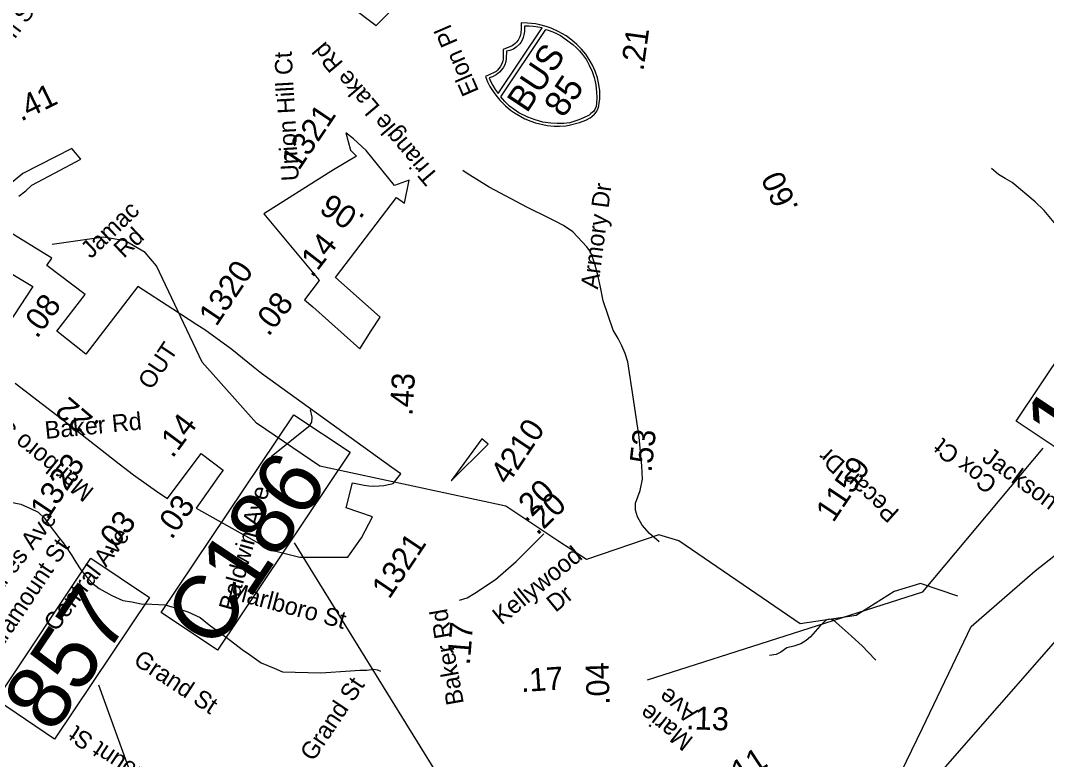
# Model space of a CAD drawing. Extents: x 1716282 to 1717158, y 799307 to 801078.
# Drawn here: x 1716895.7 to 1716976.7, y 800865.9 to 800924.3 of the extents above; entities that cross this region are included whole.
import ezdxf

# ---------------------------------------------------------------- set-up
doc = ezdxf.new("R2010")
doc.units = 0
for name, color, linetype in [('Exist Boundary Political City Limit New Hole', 7, 'Continuous'), ('Exist Hydrographic Misc Water Feature', 7, 'Continuous'), ('Exist Road Non-System Type 51', 7, 'Continuous'), ('Exist Road Non-System Type 51 Label', 7, 'Continuous'), ('Exist Road Primary Interstate Mileage Hundredths English Label', 7, 'Continuous'), ('Exist Road Primary Interstate Service Mileage Label', 7, 'Continuous'), ('Exist Road Primary Interstate Shield CELL', 7, 'Continuous'), ('Exist Road Primary Interstate Shield Number Label', 7, 'Continuous'), ('Exist Road Primary Interstate Structure Culvert Number Label', 7, 'Continuous'), ('Exist Road Primary US Structure Standard Bridge Number Label', 7, 'Continuous'), ('Exist Road Secondary Mileage Hundredths English Label', 7, 'Continuous'), ('Exist Road Secondary Mileage Tenths English Label', 7, 'Continuous'), ('Exist Road Secondary Structure Private Number Label', 7, 'Continuous'), ('Exist Road Secondary Structure Standard Bridge Number Label', 7, 'Continuous'), ('Exist Road Secondary Type 51 Label', 7, 'Continuous'), ('Exist Road Secondary Type 51 Number Label', 7, 'Continuous'), ('Exist Utilities Electrical Transmission Line', 7, 'Continuous')]:
    doc.layers.add(name, color=color, linetype=linetype)

msp = doc.modelspace()

# ---------------------------------------------------------------- linework, layer by layer
at = {"layer": 'Exist Boundary Political City Limit New Hole'}
for points in [[(1716926.548, 800926.628), (1716927.986, 800925.74), (1716928.639, 800925.355), (1716928.771, 800925.396), (1716931.477, 800928.47), (1716928.999, 800930.443), (1716931.031, 800932.976), (1716928.93, 800935.191), (1716928.099, 800935.987), (1716924.843, 800932.956), (1716921.977, 800930.288), (1716922.19, 800930.123), (1716921.362, 800929.315), (1716919.347, 800927.339), (1716920.081, 800926.73), (1716923.814, 800923.902), (1716926.548, 800926.628)], [(1716922.028, 800914.945), (1716921.442, 800915.418), (1716921.809, 800914.049), (1716922.268, 800913.565), (1716920.448, 800912.486), (1716920.03, 800912.221), (1716914.965, 800909.014), (1716919.302, 800903.797), (1716919.337, 800903.756), (1716918.172, 800902.224), (1716918.821, 800901.659), (1716922.525, 800898.348), (1716923.441, 800899.768), (1716924.135, 800900.852), (1716920.624, 800903.998), (1716925.425, 800910.305), (1716926.048, 800909.858), (1716926.43, 800911.669), (1716925.267, 800911.244), (1716923.026, 800914.015), (1716922.028, 800914.945)], [(1716895.623, 800910.42), (1716896.181, 800910.845), (1716896.65, 800911.27), (1716898.422, 800912.232), (1716900.498, 800913.331), (1716899.803, 800914.181), (1716895.92, 800912.206), (1716894.561, 800911.063)], [(1716895.333, 800895.637), (1716899.629, 800892.323), (1716903.548, 800889.268), (1716904.657, 800888.401), (1716906.674, 800886.986), (1716907.363, 800886.527), (1716910.01, 800890.071), (1716911.738, 800888.753), (1716911.488, 800888.41), (1716910.874, 800887.554), (1716910.439, 800886.933), (1716909.627, 800885.766), (1716915.483, 800882.475), (1716917.794, 800881.89), (1716920.139, 800881.9), (1716921.589, 800881.898), (1716921.784, 800882.16), (1716922.654, 800883.422), (1716923.529, 800885.081), (1716921.453, 800885.799), (1716921.943, 800887.752), (1716922.879, 800887.57), (1716923.243, 800887.525), (1716923.61, 800887.507), (1716924.068, 800887.518), (1716924.433, 800887.558), (1716924.794, 800887.622), (1716925.062, 800887.684), (1716925.165, 800887.709), (1716925.778, 800888.479), (1716925.069, 800888.986), (1716922.33, 800890.943), (1716914.77, 800896.405), (1716914.124, 800896.931), (1716912.431, 800898.286), (1716910.301, 800899.841), (1716909.676, 800900.246), (1716907.77, 800901.482), (1716905.02, 800903.264), (1716900.899, 800897.933), (1716898.619, 800899.751), (1716900.847, 800902.653), (1716897.828, 800904.931), (1716898.214, 800905.515), (1716893.19, 800908.583)], [(1716890.966, 800906.728), (1716896.721, 800903.262), (1716893.13, 800897.851)], [(1716929.755, 800887.909), (1716932.665, 800890.822), (1716932.168, 800891.227), (1716929.755, 800887.909)]]:
    msp.add_lwpolyline(points, dxfattribs=at)
at = {"layer": 'Exist Hydrographic Misc Water Feature'}
for points in [[(1716946.168, 800883.092), (1716945.395, 800883.76), (1716944.831, 800884.427), (1716944.46, 800885.065), (1716944.298, 800885.599), (1716944.295, 800886.161), (1716944.653, 800887.149), (1716944.856, 800888.063), (1716944.803, 800889.118), (1716944.703, 800890.205), (1716944.588, 800891.373), (1716944.146, 800894.379), (1716943.697, 800897.322), (1716943.488, 800897.991), (1716943.229, 800898.588), (1716942.929, 800899.179), (1716942.534, 800899.835), (1716941.749, 800902.13), (1716941.543, 800903.219), (1716941.321, 800904.179), (1716941.113, 800904.953), (1716940.925, 800905.502), (1716940.746, 800906.012), (1716940.461, 800906.416), (1716939.339, 800907.603), (1716938.621, 800908.094), (1716937.95, 800908.449), (1716937.47, 800908.672), (1716935.764, 800909.518), (1716932.75, 800911.123), (1716931, 800912.212), (1716930.665, 800912.441)], [(1716978.277, 800907.212), (1716976.554, 800909.267), (1716975.838, 800909.968), (1716974.028, 800911.484), (1716973.469, 800911.797), (1716972.95, 800912.116), (1716972.401, 800912.598)], [(1716938.162, 800883.187), (1716934.072, 800885.916), (1716919.378, 800889.067), (1716914.389, 800892.477), (1716910.099, 800897.303), (1716906.476, 800904.911), (1716905.584, 800905.96), (1716904.015, 800906.871), (1716902.31, 800907.175), (1716898.24, 800906.584)], [(1716895.118, 800886.2), (1716895.768, 800886.066), (1716896.534, 800885.744), (1716897.148, 800885.458), (1716897.629, 800884.981), (1716898.099, 800884.335), (1716898.782, 800883.436), (1716899.128, 800883.019), (1716899.471, 800882.497), (1716899.807, 800882.015), (1716900.112, 800881.485), (1716900.51, 800880.89), (1716900.965, 800880.326), (1716901.382, 800879.859), (1716901.961, 800879.42), (1716902.956, 800878.868), (1716903.817, 800878.479), (1716904.547, 800878.359), (1716905.261, 800878.216), (1716906.121, 800878.181), (1716907.175, 800878.119), (1716908.143, 800877.833), (1716908.958, 800877.582), (1716909.938, 800877.111), (1716910.643, 800876.549), (1716911.603, 800875.846), (1716912.325, 800875.309), (1716913.245, 800874.597), (1716913.815, 800874.197), (1716914.745, 800873.552), (1716915.759, 800873.128), (1716916.436, 800872.831), (1716919.452, 800872.743), (1716921.798, 800872.912), (1716922.539, 800872.961), (1716923.078, 800872.972), (1716923.651, 800873.034), (1716923.931, 800872.979), (1716924.179, 800872.878)], [(1716969.744, 800878.807), (1716966.787, 800879.81), (1716964.716, 800879.173), (1716961.707, 800877.278), (1716957.305, 800876.629), (1716947.713, 800883.172), (1716946.142, 800883.666), (1716940.425, 800881.716), (1716938.162, 800883.187)]]:
    msp.add_lwpolyline(points, dxfattribs=at)
at = {"layer": 'Exist Road Non-System Type 51'}
for points in [[(1716918.62, 800893.534), (1716918.75, 800892.947), (1716918.713, 800892.559), (1716918.49, 800892.185), (1716915.546, 800889.82)], [(1716930.401, 800878.486), (1716931.019, 800878.685), (1716931.625, 800879.036), (1716933.241, 800880.129), (1716934.869, 800881.55), (1716937.054, 800883.732)], [(1716963.275, 800873.743), (1716962.636, 800874.402), (1716962.205, 800874.861), (1716961.315, 800875.677), (1716960.385, 800876.52), (1716959.934, 800876.913), (1716959.631, 800876.987), (1716959.365, 800876.945), (1716959.113, 800876.706), (1716958.847, 800876.445), (1716958.11, 800875.591), (1716957.78, 800875.295), (1716957.336, 800875.042), (1716956.806, 800874.858), (1716956.24, 800874.727), (1716955.773, 800874.376), (1716955.413, 800874.21), (1716954.882, 800874.127)]]:
    msp.add_lwpolyline(points, dxfattribs=at)
at = {"layer": 'Exist Road Primary Interstate Shield CELL'}
for points in [[(1716941.213, 800917.065), (1716941.279, 800917.187), (1716941.351, 800917.36), (1716941.402, 800917.542), (1716941.441, 800917.763), (1716941.47, 800918.107), (1716941.487, 800918.388), (1716941.486, 800918.726), (1716941.411, 800919.232), (1716941.291, 800919.767), (1716941.102, 800920.294), (1716940.9, 800920.748), (1716940.63, 800921.209), (1716940.366, 800921.62), (1716940.026, 800922.034), (1716939.67, 800922.395), (1716939.269, 800922.726), (1716938.811, 800923.074), (1716938.253, 800923.401), (1716937.642, 800923.675), (1716937.241, 800923.816), (1716936.743, 800923.957), (1716936.41, 800924.023), (1716935.778, 800924.082), (1716935.271, 800924.095), (1716935.282, 800923.612), (1716935.252, 800923.322), (1716935.224, 800923.152), (1716935.16, 800923), (1716935.025, 800922.733), (1716934.914, 800922.582), (1716934.785, 800922.46), (1716934.677, 800922.356), (1716934.561, 800922.289), (1716933.86, 800921.987), (1716933.847, 800921.223), (1716933.824, 800921.076), (1716933.771, 800920.946), (1716933.728, 800920.815), (1716933.615, 800920.627), (1716933.517, 800920.49), (1716933.396, 800920.364), (1716933.297, 800920.267), (1716933.15, 800920.182), (1716932.442, 800919.869), (1716932.609, 800919.448), (1716932.798, 800919.068), (1716933.107, 800918.594), (1716933.366, 800918.254), (1716933.587, 800917.988), (1716934.025, 800917.549), (1716934.43, 800917.202), (1716934.736, 800916.984), (1716935.551, 800916.521), (1716936.022, 800916.329), (1716936.415, 800916.192), (1716937.331, 800915.995), (1716937.881, 800915.94), (1716938.297, 800915.931), (1716938.798, 800915.972), (1716939.048, 800916.008), (1716939.882, 800916.232), (1716940.369, 800916.428), (1716940.718, 800916.612), (1716940.86, 800916.713), (1716941.061, 800916.885)], [(1716932.735, 800919.766), (1716932.85, 800919.497), (1716933.023, 800919.16), (1716933.227, 800918.847), (1716933.459, 800918.511), (1716936.941, 800923.71), (1716936.59, 800923.77), (1716936.232, 800923.822), (1716935.893, 800923.852), (1716935.543, 800923.848), (1716935.531, 800923.433), (1716935.489, 800923.154), (1716935.434, 800922.943), (1716935.37, 800922.777), (1716935.238, 800922.541), (1716935.165, 800922.445), (1716934.885, 800922.18), (1716934.657, 800922.026), (1716934.388, 800921.915), (1716934.125, 800921.854), (1716934.099, 800921.275), (1716934.057, 800921.039), (1716933.97, 800920.793), (1716933.845, 800920.543), (1716933.569, 800920.214), (1716933.287, 800920.001), (1716933.002, 800919.844)], [(1716937.218, 800923.569), (1716937.402, 800923.527), (1716937.78, 800923.385), (1716938.058, 800923.257), (1716938.374, 800923.105), (1716938.86, 800922.759), (1716939.357, 800922.392), (1716939.63, 800922.141), (1716939.864, 800921.893), (1716940.113, 800921.601), (1716940.428, 800921.19), (1716940.645, 800920.767), (1716940.868, 800920.271), (1716941.03, 800919.787), (1716941.094, 800919.581), (1716941.177, 800919.217), (1716941.228, 800918.621), (1716941.251, 800918.195), (1716941.224, 800917.722), (1716941.185, 800917.498), (1716941.093, 800917.269), (1716940.971, 800917.112), (1716940.783, 800916.947), (1716940.63, 800916.814), (1716940.201, 800916.588), (1716939.817, 800916.429), (1716939.103, 800916.213), (1716938.628, 800916.157), (1716938.112, 800916.152), (1716937.605, 800916.18), (1716936.973, 800916.27), (1716936.384, 800916.43), (1716935.786, 800916.659), (1716935.098, 800917.004), (1716934.706, 800917.254), (1716934.35, 800917.526), (1716934.179, 800917.692), (1716933.969, 800917.901), (1716933.659, 800918.246)]]:
    msp.add_lwpolyline(points, close=True, dxfattribs=at)
at = {"layer": 'Exist Road Primary Interstate Structure Culvert Number Label'}
msp.add_line((1716938.452, 800848.887), (1716917.387, 800883.023), dxfattribs=at)
msp.add_lwpolyline([(1716906.855, 800877.507), (1716917.322, 800893.146), (1716921.764, 800890.173), (1716911.297, 800874.534)], close=True, dxfattribs=at)
at = {"layer": 'Exist Road Primary US Structure Standard Bridge Number Label'}
msp.add_line((1716930.657, 800792.469), (1716901.927, 800871.786), dxfattribs=at)
msp.add_lwpolyline([(1716893.815, 800870.614), (1716901.307, 800881.808), (1716905.936, 800878.71), (1716898.444, 800867.516)], close=True, dxfattribs=at)
at = {"layer": 'Exist Road Secondary Structure Private Number Label'}
msp.add_lwpolyline([(1716974.349, 800892.644), (1716981.982, 800904.048), (1716986.639, 800900.931), (1716979.006, 800889.526)], close=True, dxfattribs=at)
msp.add_lwpolyline([(1716945.236, 800872.188), (1716966.974, 800879.147), (1716976.472, 800890.503)], dxfattribs=at)
at = {"layer": 'Exist Road Secondary Structure Standard Bridge Number Label'}
msp.add_line((1716964.807, 800860.796), (1716992.417, 800892.393), dxfattribs=at)
at = {"layer": 'Exist Utilities Electrical Transmission Line'}
msp.add_lwpolyline([(1716944.8, 800799.971), (1716945.692, 800811.122), (1716946.399, 800819.65), (1716947.188, 800829.422), (1716951.09, 800836.913), (1716954.684, 800844.014), (1716957.855, 800849.995), (1716960.182, 800854.593), (1716961.868, 800857.902), (1716966.945, 800868.385), (1716970.788, 800876.406), (1716975.857, 800880.798), (1716979.659, 800883.813)], dxfattribs=at)

# ---------------------------------------------------------------- texts
at = {"layer": 'Exist Boundary Political City Limit New Hole'}
msp.add_text('OUT', height=1.3775, rotation=56.20506, dxfattribs=at).set_placement((1716906.071, 800895.033))
at = {"layer": 'Exist Road Non-System Type 51 Label'}
for s, rotation, p in [('Pam St', 53.3829, (1716893.625, 800920.535)), ('Triangle Lake Rd', 130.26838, (1716928.823, 800912.013)), ('Union Hill Ct', 93.23093, (1716917.726, 800911.64)), ('Armory Dr', 82.57819, (1716941.331, 800903.02)), ('Marlboro St', 141.03594, (1716901.639, 800887.228)), ('Charles Ave', 52.18944, (1716892.522, 800876.971)), ('Central Ave', 52.35306, (1716898.551, 800875.939)), ('Paramount St', 56.20506, (1716893.41, 800873.393)), ('Marlboro St', 345.06802, (1716912.032, 800878.667)), ('Grand St', 326.55755, (1716904.573, 800873.503)), ('Grand St', 56.20506, (1716918.865, 800865.688)), ('Paramount St', 146.53214, (1716909.549, 800862.44))]:
    msp.add_text(s, height=1.3775, rotation=rotation, dxfattribs=at).set_placement(p)
at = {"layer": 'Exist Road Primary Interstate Mileage Hundredths English Label'}
for s, rotation, p in [('.21', 82.1108, (1716944.92, 800920.253)), ('.53', 83.7115, (1716945.555, 800888.545)), ('.04', 91.66842, (1716942.26, 800870.234))]:
    msp.add_text(s, height=1.8125, rotation=rotation, dxfattribs=at).set_placement(p)
at = {"layer": 'Exist Road Primary Interstate Service Mileage Label'}
msp.add_text('.11', height=1.8125, rotation=33.3761, dxfattribs=at).set_placement((1716952.057, 800863.597))
at = {"layer": 'Exist Road Primary Interstate Shield Number Label'}
for s, p in [('BUS', (1716935.72, 800916.913)), ('85', (1716938.626, 800916.528))]:
    msp.add_text(s, height=2.03, rotation=56.20506, dxfattribs=at).set_placement(p)
at = {"layer": 'Exist Road Primary Interstate Structure Culvert Number Label'}
msp.add_text('C186', height=5.075, rotation=56.20506, dxfattribs=at).set_placement((1716911.094, 800874.39))
at = {"layer": 'Exist Road Primary US Structure Standard Bridge Number Label'}
msp.add_text('857', height=5.075, rotation=56.20506, dxfattribs=at).set_placement((1716898.306, 800867.826))
at = {"layer": 'Exist Road Secondary Mileage Hundredths English Label'}
for s, rotation, p in [('.41', 25.92016, (1716895.783, 800916.291)), ('.06', 146.17015, (1716923.039, 800908.821)), ('.14', 53.34477, (1716907.751, 800889.649)), ('.03', 55.47933, (1716907.683, 800883.21)), ('.17', 85.33445, (1716931.212, 800873.326)), ('.17', 3.73987, (1716935.286, 800871.23)), ('.13', 358.12593, (1716948.277, 800868.303))]:
    msp.add_text(s, height=1.8125, rotation=rotation, dxfattribs=at).set_placement(p)
at = {"layer": 'Exist Road Secondary Mileage Tenths English Label'}
for s, rotation, p in [('.60', 114.63469, (1716957.204, 800909.498)), ('.14', 52.17416, (1716918.771, 800903.912)), ('.08', 53.75287, (1716897.045, 800899.095)), ('.08', 52.35953, (1716915.326, 800899.262)), ('.43', 86.45566, (1716926.69, 800893.032)), ('.22', 139.6181, (1716902.09, 800892.468)), ('.20', 44.24855, (1716935.637, 800884.558)), ('.20', 44.24855, (1716936.546, 800883.554)), ('.03', 51.57382, (1716902.869, 800881.992))]:
    msp.add_text(s, height=1.8125, rotation=rotation, dxfattribs=at).set_placement(p)
at = {"layer": 'Exist Road Secondary Structure Private Number Label'}
msp.add_text('196', height=5.075, rotation=56.20506, dxfattribs=at).set_placement((1716978.869, 800889.837))
at = {"layer": 'Exist Road Secondary Type 51 Label'}
for s, rotation, p in [('Elon Pl', 113.44952, (1716931.962, 800918.706)), ('Jamac', 43.51904, (1716901.301, 800905.416)), (' Rd', 43.51904, (1716903.535, 800905.098)), ('Baker Rd', 5.63289, (1716897.728, 800891.23)), ('Cox Ct', 141.71839, (1716972.949, 800887.875)), ('Pecan Dr', 138.01422, (1716965.21, 800885.521)), ('Jackson Lake Rd', 323.82883, (1716971.557, 800889.558)), ('Baldwin Ave', 74.40071, (1716912.697, 800877.529)), ('Kellywood', 39.32041, (1716933.713, 800876.49)), (' Dr', 39.32041, (1716937.587, 800877.157)), ('Baker Rd', 100.10466, (1716930.751, 800870.338)), (' Ave', 141.9396, (1716949.722, 800869.418)), ('Marie', 141.9396, (1716948.946, 800867.563))]:
    msp.add_text(s, height=1.3775, rotation=rotation, dxfattribs=at).set_placement(p)
at = {"layer": 'Exist Road Secondary Type 51 Number Label'}
for s, p in [('1321', (1716917.724, 800912.376)), ('1320', (1716911.202, 800900.047)), ('4210', (1716934.212, 800887.534)), ('1323', (1716897.882, 800884.79)), ('1159', (1716959.909, 800884.559)), ('1321', (1716924.854, 800878.509))]:
    msp.add_text(s, height=1.8125, rotation=56.20506, dxfattribs=at).set_placement(p)

doc.saveas('drawing.dxf')
